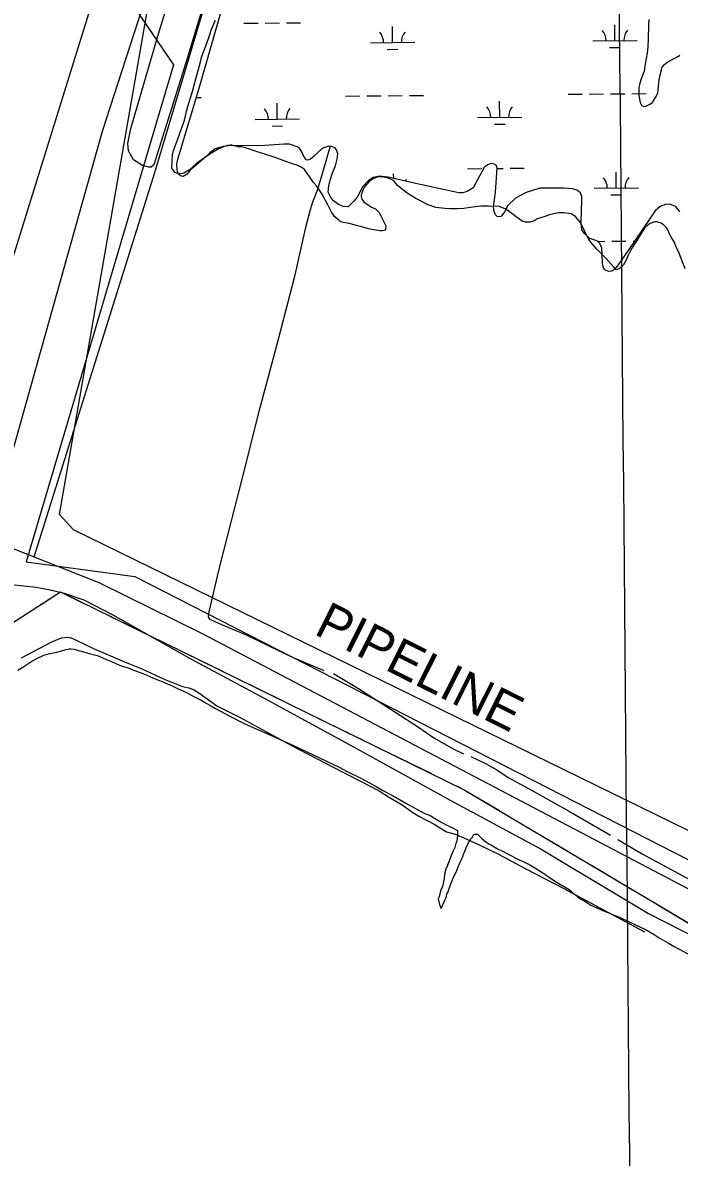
# Model space of a CAD drawing. Extents: x 3567028 to 3605064, y 510945 to 536587.
# Drawn here: x 3596245 to 3597727, y 517794 to 520355 of the extents above; entities that cross this region are included whole.
import ezdxf

# ---------------------------------------------------------------- set-up
doc = ezdxf.new("R2010")
doc.units = 0
for name, color, linetype in [('V-DTCH-CNTR', 7, 'Continuous'), ('V-GRID-MAJR', 7, 'Continuous'), ('V-SITE-VEGE', 7, 'Continuous'), ('V-TOPO-SHOR', 7, 'Continuous'), ('V-UTIL-IDEN', 7, 'Continuous'), ('V-UTIL-LINE', 7, 'Continuous'), ('V-WETL-SWMP', 7, 'Continuous')]:
    doc.layers.add(name, color=color, linetype=linetype)

msp = doc.modelspace()

# ---------------------------------------------------------------- linework, layer by layer
at = {"layer": 'V-DTCH-CNTR'}
msp.add_lwpolyline([(3595962.4, 519136.7), (3595998.9, 519139.6), (3596031.9, 519138.3), (3596069.7, 519130.3), (3596147.5, 519102.4), (3596219.4, 519087), (3596275.4, 519081), (3596307.2, 519074.8), (3596338.3, 519067.4), (3596382.6, 519052.4), (3596448.3, 519018.5), (3596621.6, 518920.9), (3596789.8, 518830.2), (3596991.3, 518720.9), (3597209.8, 518600.4), (3597414.8, 518489.3), (3597657.1, 518344.1), (3597882.6, 518229.5), (3598061.5, 518138.4)], dxfattribs=at)
at = {"layer": 'V-GRID-MAJR'}
msp.add_spline([(3597625.7, 516571.7), (3597572.8, 522630.5), (3597519.9, 528691.2), (3597467, 534752), (3597467, 534753.9)], degree=3, dxfattribs=at)
at = {"layer": 'V-SITE-VEGE'}
msp.add_lwpolyline([(3596540.6, 520034), (3596534.7, 520028.9), (3596529.5, 520029), (3596514.9, 520032.7), (3596495.2, 520045.4), (3596483.6, 520066), (3596482.3, 520082.2), (3596489.2, 520116.6), (3596551.2, 520330.3), (3596611.5, 520526.4), (3596616.7, 520536.6), (3596624.9, 520542.4), (3596684.3, 520550), (3596693.9, 520547.7), (3596699.7, 520541), (3596696.7, 520533), (3596682.4, 520493.5), (3596613, 520264.5)], close=True, dxfattribs=at)
for points in [[(3596885.3, 520017.1), (3596880.8, 520024), (3596873.4, 520029.2), (3596865.4, 520032.7), (3596851.6, 520036.9), (3596824.1, 520046.9), (3596814.4, 520051), (3596789.2, 520059.2), (3596774.3, 520063.4), (3596765.8, 520066.9), (3596754.3, 520070.4), (3596748, 520072.8), (3596738.3, 520074.6), (3596731.4, 520075.2), (3596726.8, 520076.4), (3596721.6, 520077), (3596717.1, 520078.8), (3596713.6, 520078.8), (3596707.3, 520077.7), (3596699.2, 520075.5), (3596684.3, 520068.7), (3596673.3, 520061.9), (3596657.7, 520051.7), (3596636.9, 520037), (3596630.6, 520031.3), (3596621.3, 520023.3), (3596608.6, 520015.4), (3596602.3, 520013.7), (3596592.5, 520015.5), (3596588, 520017.3), (3596583.4, 520023.7), (3596581.7, 520027.1), (3596581.9, 520042.6), (3596583.1, 520056.4), (3596585.5, 520066.7), (3596593.2, 520088.4), (3596599.6, 520105.6), (3596607.9, 520128.5), (3596610.2, 520135.4), (3596616.2, 520160.6), (3596617.4, 520166.3), (3596622.7, 520183.5), (3596628, 520199.5), (3596635.7, 520228.1), (3596645.8, 520267.1), (3596648.7, 520277.4), (3596654.6, 520293.4), (3596658.7, 520304.3), (3596666.4, 520326), (3596671.1, 520340.4), (3596679.9, 520361)], [(3597658, 520362.4), (3597656.8, 520350.9), (3597656.5, 520318.2), (3597655.8, 520300.4), (3597653.9, 520286.1), (3597649.7, 520262.6), (3597647.3, 520246), (3597640.2, 520228.2), (3597637.3, 520218.5), (3597635.5, 520208.2), (3597635.3, 520191), (3597638.6, 520174.9), (3597640.9, 520169.1), (3597646.6, 520165.6), (3597651.2, 520166.7), (3597660.4, 520171.2), (3597666.2, 520175.2), (3597669.1, 520180.3), (3597672.6, 520186.1), (3597677.9, 520196.3), (3597681, 520226.2), (3597683.4, 520237.1), (3597687.5, 520254.8), (3597692.8, 520261.1), (3597698.5, 520265.1)], [(3597698.5, 520265.1), (3597710.1, 520271.8), (3597718.1, 520275.8), (3597724.5, 520279.8), (3597728, 520281.5)], [(3597692, 519898.3), (3597685.7, 519902.4), (3597676, 519905.9), (3597670.8, 519905.9), (3597667.9, 519904.2), (3597661, 519902), (3597656.4, 519898.6), (3597648.3, 519891.2), (3597632.6, 519867.2), (3597628.5, 519859.8), (3597623.3, 519852.4), (3597619.2, 519846.1), (3597614.5, 519836.4), (3597611, 519830.1), (3597606.4, 519818.7), (3597600.5, 519808.9), (3597590.7, 519799.3), (3597584.4, 519797.6), (3597578.7, 519803.4), (3597573, 519810.3), (3597561.6, 519822.5), (3597553.6, 519831.2), (3597546.8, 519838.1), (3597540.6, 519843.9), (3597530.3, 519854.9), (3597524.6, 519862.4), (3597517.3, 519875.7), (3597513.3, 519883.7), (3597507.7, 519896.4), (3597503.2, 519905.1), (3597492.4, 519917.8), (3597482.7, 519923.6), (3597466, 519926), (3597453.4, 519925.6), (3597433.9, 519921.7), (3597422.9, 519917.8), (3597413.1, 519914.4), (3597406.2, 519912.2), (3597396.4, 519907.1), (3597390.1, 519904.9), (3597379.8, 519905), (3597371.7, 519907.3), (3597358.6, 519916.6), (3597348.9, 519924.7), (3597333.5, 519934.6), (3597319.8, 519939.9), (3597296.3, 519941.3), (3597278.5, 519940.8), (3597254.9, 519937.6), (3597240, 519935.4), (3597226.2, 519935), (3597208.4, 519935.1), (3597197.5, 519935.8), (3597176.8, 519938.3), (3597159.7, 519944.1), (3597131.7, 519958.2), (3597112.8, 519970.4), (3597090.6, 519987.8), (3597081.5, 519998.8), (3597079.8, 519999.9), (3597067.8, 520005.2), (3597055.1, 520007), (3597046.5, 520007.1), (3597033.9, 520002), (3597026.4, 519996.4), (3597016.5, 519984.4), (3597012.4, 519977), (3597008.9, 519966.1), (3597008.8, 519962.6), (3597010.5, 519956.9), (3597014.5, 519951.1), (3597025.3, 519943), (3597032.2, 519938.9), (3597040.8, 519934.8), (3597044.7, 519931.3), (3597048.7, 519927.3), (3597053.3, 519919.2), (3597060, 519905.4), (3597064, 519896.2), (3597063.9, 519889.3), (3597061, 519886.4), (3597056.4, 519885.3), (3597050.7, 519885.4), (3597036.3, 519887.8), (3597024.9, 519889.6), (3597010, 519894.3), (3597000.3, 519896.7), (3596987.7, 519900.3), (3596977.9, 519902.6), (3596968.2, 519904.4), (3596960.2, 519906.8), (3596948.8, 519917.8), (3596941.4, 519927.6), (3596933.5, 519943.8), (3596927.8, 519954.1), (3596920.5, 519968), (3596916, 519974.9), (3596908, 519986.5), (3596901.2, 519994.6), (3596890.4, 520010.1), (3596885.3, 520017.1)], [(3597739.4, 519799.7), (3597726.5, 519834.9), (3597718.6, 519851), (3597714.6, 519860.2), (3597707.8, 519872.3), (3597703.9, 519879.8), (3597701.1, 519886.2), (3597697.7, 519891.9), (3597692, 519898.3)], [(3596234, 518893.5), (3596245, 518900.3), (3596263.4, 518912.2), (3596275.6, 518918.9), (3596292.8, 518927.4), (3596303.2, 518930.2), (3596314.7, 518932.4), (3596322.2, 518934), (3596332.5, 518937.4), (3596340, 518939.6), (3596349.8, 518941.9), (3596354.4, 518941.8), (3596361.3, 518941.2), (3596369.9, 518937.7), (3596377.9, 518936.4), (3596391.6, 518931.7), (3596400.8, 518929.4), (3596412.8, 518927), (3596420.3, 518923.5), (3596434, 518917.6), (3596445.4, 518912.9), (3596456.9, 518907.6), (3596467.2, 518903.5), (3596484.9, 518898.2), (3596491.2, 518895.3), (3596507.8, 518889.4), (3596518.1, 518885.3), (3596531.8, 518879.5), (3596539.8, 518875.4), (3596547.3, 518872.4), (3596551.3, 518870.7), (3596559.3, 518868.3), (3596566.7, 518864.8), (3596582.2, 518858.4), (3596594.2, 518852.5), (3596614.2, 518843.2)], [(3596614.2, 518843.2), (3596627.9, 518835.6), (3596647.3, 518825.7), (3596658.7, 518819.3), (3596669.6, 518813.4), (3596678.2, 518807.6), (3596713.6, 518788.9), (3596744.5, 518773.2), (3596766.2, 518763.2), (3596802.8, 518747.4), (3596825.7, 518736.9), (3596856, 518723.4), (3596914.9, 518695.4), (3596958.9, 518674.9), (3596977.2, 518665), (3597004.6, 518651), (3597018.9, 518644), (3597042.3, 518631.2), (3597057.2, 518621.9), (3597080.6, 518609.6), (3597095.5, 518601.4), (3597109.2, 518593.3), (3597130.9, 518581.6), (3597152, 518570), (3597164, 518565.3), (3597188, 518551.3), (3597204.6, 518542), (3597216, 518536.7), (3597224.6, 518532.6), (3597226.3, 518531.4), (3597226.2, 518520), (3597224.4, 518508.5), (3597222.1, 518502.2), (3597219.7, 518493), (3597216.8, 518487.3), (3597212.7, 518477), (3597208.6, 518467.3), (3597203.8, 518452.4), (3597199.8, 518444.4), (3597196.8, 518433), (3597195.6, 518422.6), (3597192, 518405.4), (3597187.9, 518395.7), (3597184.3, 518382), (3597182.5, 518377.4), (3597186.4, 518361.9), (3597189.2, 518355.5), (3597192.2, 518362.4), (3597196.3, 518371), (3597201, 518383), (3597202.2, 518388.7), (3597205.1, 518393.3), (3597206.3, 518398.4), (3597213.9, 518419), (3597218, 518427.6), (3597223.2, 518437.9), (3597225.6, 518443.6), (3597229.1, 518453.3), (3597232, 518459.1), (3597235.6, 518468.8), (3597237.9, 518472.8), (3597239.7, 518478.5), (3597242, 518483.1), (3597245.5, 518492.2), (3597247.9, 518498), (3597251.9, 518506), (3597253.1, 518507.7), (3597256, 518514), (3597258.9, 518516.2), (3597261.8, 518522), (3597265.3, 518523.6), (3597271, 518523.6), (3597273.9, 518520.1), (3597281.3, 518513.8), (3597287, 518508.5), (3597296.7, 518501.6), (3597302.4, 518498.6), (3597316.1, 518490.5), (3597325.8, 518485.8), (3597363.5, 518466), (3597378.4, 518459.5), (3597390.4, 518453.7), (3597404.1, 518445.5), (3597412.1, 518440.3), (3597423.5, 518432.2), (3597433.2, 518426.4), (3597445.2, 518418.2), (3597454.9, 518411.8), (3597477.8, 518398.4), (3597490.3, 518388), (3597500, 518379.3), (3597513.1, 518372.3), (3597526.8, 518363), (3597550.3, 518352.5), (3597594.9, 518334.3), (3597613.2, 518325.5), (3597637.8, 518314.4), (3597652.1, 518307.4), (3597669.8, 518296.9), (3597681.2, 518289.4), (3597702.3, 518277.1)], [(3597702.3, 518277.1), (3597716.6, 518269), (3597758.3, 518246.8)]]:
    msp.add_lwpolyline(points, dxfattribs=at)
at = {"layer": 'V-TOPO-SHOR'}
for points in [[(3596938.4, 520076.1), (3596924, 520024.3), (3596910.4, 519978.9), (3596899.2, 519949.9), (3596893.3, 519932.6), (3596882.5, 519889.6), (3596857.8, 519779), (3596818.7, 519628.6), (3596777.1, 519474.5), (3596741.2, 519330.5), (3596697.7, 519163), (3596686.9, 519118.2), (3596664.7, 519025.1), (3596663.2, 519014.7), (3596664.4, 519011.9), (3596666.3, 519008.6), (3596669.8, 519007), (3596693.6, 518996.9), (3596748.9, 518973.6), (3596850.2, 518924.2), (3596924.7, 518892.5)], [(3596242.2, 518921.2), (3596310.8, 518957.8), (3596332.2, 518966.5), (3596346.9, 518968.3), (3596354.5, 518966.5), (3596365.3, 518961.3), (3596405, 518942.8), (3596474.8, 518912.5), (3596512, 518897.4), (3596563.8, 518873.3), (3596605.7, 518856.5), (3596619.7, 518853.4), (3596630.2, 518850), (3596642, 518842.8), (3596682.6, 518813.2), (3596735.3, 518787.1), (3596851.2, 518723.7), (3596947, 518674.1), (3597033.6, 518629.5)], [(3596945.9, 518886.2), (3597002.3, 518852.2), (3597084.7, 518799.4), (3597138, 518764.7), (3597172.8, 518740.6), (3597195.5, 518727.8), (3597218, 518715.2), (3597239.4, 518704.8)], [(3597256.1, 518698.8), (3597291, 518682.3), (3597314.5, 518668.6), (3597340.3, 518651.6), (3597394.2, 518621.8), (3597480.4, 518573.9), (3597571.4, 518521)], [(3597033.6, 518629.5), (3597051.4, 518619.5), (3597070.7, 518607.6), (3597101.2, 518590), (3597123.2, 518573.5), (3597139, 518563.8), (3597173.5, 518546), (3597201.4, 518528.6), (3597221.1, 518523.6), (3597240.1, 518515), (3597273.6, 518500.3), (3597318.4, 518478.3), (3597379, 518446), (3597465.9, 518400.9), (3597565.3, 518347.4), (3597648.2, 518302.9)], [(3597588.2, 518511.4), (3597641.3, 518479.6), (3597724.4, 518434.9), (3597755.6, 518418.3), (3597783.4, 518399.5), (3597808.4, 518385.5), (3597831.1, 518372.6), (3597838.8, 518369.1), (3597848.2, 518366.7), (3597854.7, 518366.6), (3597866.1, 518363.6), (3597920.8, 518345.7)]]:
    msp.add_lwpolyline(points, dxfattribs=at)
at = {"layer": 'V-UTIL-LINE'}
for points in [[(3593722.3, 520581), (3593792.3, 520296.6), (3593801.9, 520296.7), (3593896.1, 520296.1), (3594592.4, 520277.2), (3594978.9, 520291.6), (3595334, 520311.4), (3595594.8, 520332.4), (3596449.3, 520461.1), (3596585, 520260.3), (3596252.5, 519138.1), (3596497.9, 519105.4), (3599194.1, 517725.2), (3599314.9, 517613.9), (3599409.7, 517389.2), (3599477, 517244.3), (3601053, 517177.2), (3601020.6, 516600.3)], [(3596701.4, 520550.8), (3596542.3, 520016.3), (3596269.7, 519148.8)], [(3601082.8, 516600.9), (3601098.4, 516822), (3601121.9, 517167.6), (3599557.2, 517264.8), (3599483.9, 517358.5), (3599393.5, 517475.6), (3599227.5, 517653.1), (3598990.7, 517923), (3596359.6, 519210.3), (3596327.8, 519244.7), (3596555.7, 520553.5)], [(3599361.9, 517381.5), (3599253.3, 517550.7), (3599144.6, 517684), (3598801.1, 517874.5), (3597968.3, 518283.7), (3596650.6, 518975.6), (3596417.4, 519090.5), (3596166, 519189.8), (3596424.9, 520110.5), (3596559.2, 520523.7)], [(3596431.7, 520499.1), (3596072.9, 519346), (3595983.9, 519028.5), (3595942.5, 518820.2)], [(3592391.9, 517062.8), (3593369.1, 517526.2), (3594582.6, 518135.5), (3595477.2, 518582.3), (3595939.8, 518818.4), (3596329.9, 519070.3), (3597241.4, 518623.6), (3597895.1, 518235.1), (3598852.4, 517733.3), (3599147.3, 517541.9), (3599253.9, 517354.5)], [(3596287.4, 519042.9), (3596329.9, 519070.3), (3596381.7, 519045)], [(3596441.5, 519015.6), (3596538.8, 518968)], [(3596598.6, 518938.7), (3596695.8, 518891)], [(3596755.6, 518861.7), (3596852.9, 518814)], [(3596912.7, 518784.7), (3597009.9, 518737.1)], [(3597069.7, 518707.8), (3597167, 518660.1)], [(3597226.8, 518630.8), (3597241.4, 518623.6), (3597320.5, 518576.6)], [(3597377.8, 518542.6), (3597470.9, 518487.3)], [(3597528.1, 518453.2), (3597621.2, 518397.9)], [(3597678.4, 518363.9), (3597771.5, 518308.5)]]:
    msp.add_lwpolyline(points, dxfattribs=at)
at = {"layer": 'V-WETL-SWMP'}
for p, q in [((3596744.1, 520354), (3596776.1, 520354.2)), ((3596792.1, 520354.4), (3596824.1, 520354.6)), ((3596840.1, 520354.8), (3596872.1, 520355)), ((3597079.4, 520310.4), (3597079.1, 520346.4)), ((3597581.3, 520314.6), (3597581, 520350.6)), ((3597029.4, 520309.9), (3597129.4, 520310.8)), ((3597531.3, 520314.2), (3597631.3, 520315)), ((3597067.5, 520294.8), (3597091.5, 520295)), ((3597569.4, 520299.1), (3597593.4, 520299.3)), ((3596637.1, 520186.6), (3596647.6, 520186.6)), ((3596973.5, 520189.4), (3597005.5, 520189.7)), ((3597021.5, 520189.8), (3597053.5, 520190.1)), ((3597069.5, 520190.2), (3597101.5, 520190.5)), ((3597117.5, 520190.6), (3597149.5, 520190.9)), ((3597475.4, 520193.6), (3597507.4, 520193.9)), ((3597523.4, 520194), (3597555.4, 520194.3)), ((3597571.4, 520194.4), (3597603.4, 520194.7)), ((3597619.4, 520194.8), (3597651.4, 520195.1)), ((3596819.4, 520137.4), (3596819.1, 520173.4)), ((3597321.3, 520141.6), (3597321, 520177.6)), ((3596769.4, 520136.9), (3596869.4, 520137.8)), ((3597271.3, 520141.2), (3597371.3, 520142)), ((3596807.5, 520121.8), (3596831.5, 520122)), ((3597309.4, 520126.1), (3597333.4, 520126.3)), ((3597082, 520003.7), (3597081.9, 520013.7)), ((3597248.8, 520025.5), (3597280.8, 520025.8)), ((3597315.2, 520026.1), (3597328.8, 520026.2)), ((3597344.8, 520026.4), (3597376.8, 520026.6)), ((3597584.1, 519981.9), (3597583.8, 520017.9)), ((3597534.1, 519981.5), (3597634.1, 519982.4)), ((3597572.2, 519966.4), (3597596.2, 519966.6)), ((3597541.9, 519861.5), (3597558.2, 519861.6)), ((3597574.2, 519861.8), (3597606.2, 519862)), ((3597622.2, 519862.2), (3597625.5, 519862.2))]:
    msp.add_line(p, q, dxfattribs=at)
for points in [[(3597238.1, 519971.2), (3597229.4, 519971.1), (3597134.8, 519991.4), (3597069.6, 520006.5), (3597049, 520008.9), (3597036.7, 520005.8), (3597024.2, 519998.1), (3597012.1, 519985.3), (3597005.5, 519972.4), (3596999.3, 519961.6), (3596992.1, 519952), (3596989.3, 519948.9), (3596979.2, 519939.3), (3596967.7, 519940.2), (3596957.3, 519944.8), (3596946.4, 519953), (3596939.3, 519962.3), (3596934.5, 519972.8), (3596935.4, 519986.8), (3596938.5, 520000), (3596944.3, 520016.1), (3596950.8, 520032), (3596954.8, 520046.9), (3596955.9, 520058.8), (3596953.2, 520068.3), (3596949.3, 520073), (3596942.7, 520075.6), (3596935, 520076.5), (3596920.9, 520070.9), (3596910.4, 520061.7), (3596902.3, 520053.9), (3596894.1, 520047.1), (3596888.2, 520044.9), (3596884.8, 520045.8), (3596878, 520055.7), (3596874.5, 520063.6), (3596868.3, 520073.7), (3596854, 520078.7), (3596846.7, 520080.8), (3596834.1, 520080.7), (3596780.8, 520077.2), (3596714.2, 520077.6), (3596697, 520075.7), (3596679.2, 520070), (3596667.3, 520061.2), (3596658.6, 520053.4), (3596647.8, 520043), (3596631.6, 520030.1), (3596622.2, 520021.2), (3596615.8, 520013.1), (3596607.1, 520008.1), (3596602.6, 520008.9), (3596595.5, 520013.9), (3596593.4, 520023), (3596593, 520035.8), (3596595.2, 520047.4), (3596604.6, 520079.1), (3596644.9, 520212.2), (3596693.9, 520385.5)], [(3597728.1, 519928.1), (3597719.5, 519939.2), (3597705.3, 519945.2), (3597695.1, 519944.7), (3597683.2, 519940.5), (3597672.1, 519930.5), (3597630.6, 519869.5), (3597592.1, 519814.1), (3597581.3, 519799), (3597574.3, 519794.3), (3597566.7, 519793.8), (3597558.6, 519797.4), (3597554.5, 519803.1), (3597553, 519813.2), (3597552.2, 519831.8), (3597551.7, 519846.3), (3597547.5, 519856.6), (3597541.6, 519861.8), (3597533.3, 519864.8), (3597524.7, 519868.1), (3597512.6, 519879.2), (3597506.9, 519887.5), (3597504.9, 519901.9), (3597505.4, 519915.1), (3597505.6, 519922.6), (3597506.8, 519962.7), (3597503.9, 519971), (3597495.6, 519976.9), (3597486.6, 519980.2), (3597466.9, 519981.9), (3597411.5, 519981.8), (3597381.2, 519972), (3597356.9, 519959.2), (3597339.8, 519942.6), (3597332.2, 519928.4), (3597328.6, 519922.7), (3597323.6, 519917.9), (3597319.3, 519916.7), (3597315.7, 519917.3), (3597312, 519921.1), (3597308.9, 519929), (3597307, 519939.5), (3597311.7, 519972.4), (3597315.3, 520027), (3597313.2, 520033.7), (3597308.6, 520036.1), (3597302.1, 520037.1), (3597293.6, 520034.2), (3597286.3, 520028.4), (3597261.3, 519982.7), (3597248.2, 519974.1), (3597238.1, 519971.2)]]:
    msp.add_lwpolyline(points, dxfattribs=at)
for centre, start, end in [((3597526, 520314.6), 359.7115, 41.2552), ((3597636.5, 520315.5), 139.7115, 181.2552), ((3597024.1, 520310.4), 359.7115, 41.2552), ((3597134.6, 520311.3), 139.7115, 181.2552), ((3596764.1, 520137.4), 359.7115, 41.2552), ((3596874.6, 520138.3), 139.7115, 181.2552), ((3597266, 520141.6), 359.7115, 41.2552), ((3597376.5, 520142.5), 139.7115, 181.2552), ((3597528.8, 519981.9), 359.7115, 41.2552), ((3597639.3, 519982.9), 139.7115, 181.2552), ((3597137.4, 519978.6), 139.7115, 147.2916)]:
    msp.add_arc(centre, 35.2, start, end, dxfattribs=at)

# ---------------------------------------------------------------- texts
at = {"layer": 'V-UTIL-IDEN'}
msp.add_text('PIPELINE', height=83, rotation=333.3559, dxfattribs=at).set_placement((3596899.6, 518976.3))

doc.saveas('drawing.dxf')
